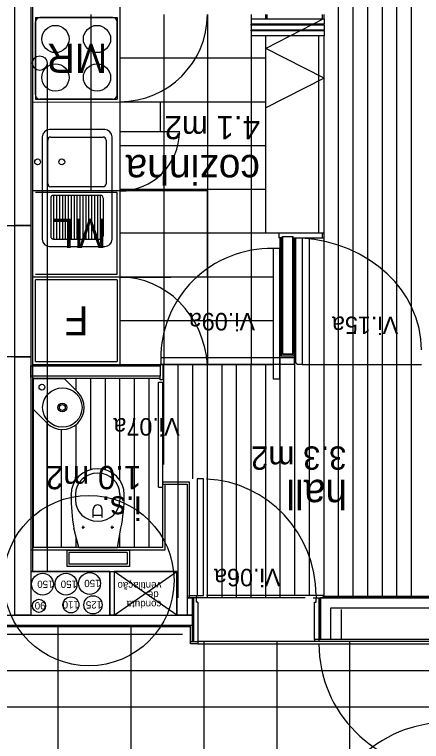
# Model space of a CAD drawing. Extents: x 1248 to 1356, y -443 to -224.
# Drawn here: x 1334.72 to 1337.511, y -239.409 to -234.424 of the extents above; entities that cross this region are included whole.
import ezdxf

# ---------------------------------------------------------------- set-up
doc = ezdxf.new("R2010")
doc.units = 0
for name, color, linetype in [('corte', 7, 'Continuous'), ('estereoctomias', 7, 'Continuous'), ('ind-pormenores', 7, 'Continuous'), ('Level 1', 7, 'Continuous'), ('Level 10', 7, 'Continuous'), ('Level 11', 7, 'Continuous'), ('Level 13', 7, 'Continuous'), ('Level 2', 7, 'Continuous'), ('Level 3', 7, 'Continuous'), ('Level 31', 7, 'Continuous'), ('Level 4', 7, 'Continuous'), ('Level 40', 7, 'Continuous'), ('Level 41', 7, 'Continuous'), ('Level 60', 7, 'Continuous'), ('mob-fixo', 7, 'Continuous'), ('revestimentos', 7, 'Continuous'), ('vista', 7, 'Continuous')]:
    doc.layers.add(name, color=color, linetype=linetype)

msp = doc.modelspace()

# ---------------------------------------------------------------- linework, layer by layer
at = {"layer": 'corte'}
for p, q in [((1334.7233, -238.544), (1334.7233, -232.0639)), ((1335.7533, -238.094), (1335.7533, -237.644)), ((1334.8333, -238.094), (1335.7533, -238.094)), ((1335.3733, -238.244), (1335.3733, -238.544)), ((1335.4033, -238.244), (1335.4033, -238.544)), ((1335.8333, -238.244), (1335.8333, -238.544)), ((1340.0033, -238.424), (1336.8183, -238.424)), ((1332.3825, -238.544), (1335.8333, -238.544)), ((1335.9033, -238.544), (1335.9383, -238.544)), ((1335.9383, -238.614), (1332.3125, -238.614))]:
    msp.add_line(p, q, dxfattribs=at)
msp.add_lwpolyline([(1334.6025, -235.8713), (1334.8325, -235.8713), (1334.8325, -236.7713), (1334.6025, -236.7713)], close=True, dxfattribs=at)
at = {"layer": 'estereoctomias'}
for p, q in [((1335.9033, -237.644), (1335.9033, -238.424)), ((1335.9033, -238.424), (1335.9458, -238.424)), ((1336.7783, -238.724), (1335.9783, -238.724))]:
    msp.add_line(p, q, dxfattribs=at)
for points in [[(1334.8333, -235.8713), (1334.7233, -235.8713), (1334.7233, -232.264), (1334.8333, -232.264), (1334.8325, -235.8713)], [(1336.6283, -236.754), (1336.5583, -236.754), (1336.5583, -235.946), (1336.6283, -235.946), (1336.6283, -236.754)], [(1335.9033, -237.644), (1335.9033, -238.424), (1335.9383, -238.424), (1335.9383, -238.544), (1335.9033, -238.544), (1335.8333, -238.544), (1335.8333, -238.244), (1335.4033, -238.244), (1335.4033, -238.544), (1335.3733, -238.544), (1335.3733, -238.244), (1334.8333, -238.244), (1334.8333, -238.544), (1334.7233, -238.544), (1334.7233, -236.7713), (1334.8333, -236.7713), (1334.8333, -238.094), (1335.7533, -238.094), (1335.7533, -237.644)], [(1340.0733, -236.7713), (1340.0733, -238.4784), (1340.0733, -238.494), (1336.8883, -238.494), (1336.8883, -238.709), (1336.8183, -238.709), (1336.8183, -238.424), (1340.0033, -238.424), (1340.0033, -236.7713)], [(1335.7183, -236.834), (1335.7183, -236.904), (1334.8333, -236.904), (1334.8333, -236.914), (1334.8333, -236.834)], [(1335.9383, -238.544), (1335.9383, -238.614), (1332.3125, -238.614), (1332.3125, -238.494), (1332.3825, -238.494), (1332.3825, -238.544), (1335.9383, -238.544)]]:
    msp.add_lwpolyline(points, close=True, dxfattribs=at)
at = {"layer": 'ind-pormenores'}
msp.add_circle((1335.2301, -238.3059), 0.5842, dxfattribs=at)
at = {"layer": 'Level 1'}
for p, q in [((1334.8333, -232.264), (1334.8333, -238.544)), ((1336.4433, -234.456), (1336.4433, -234.424)), ((1336.4533, -234.456), (1336.4533, -234.424)), ((1336.8333, -234.456), (1336.8333, -234.424)), ((1336.8433, -234.456), (1336.8433, -234.424)), ((1336.8433, -234.456), (1336.4433, -234.456)), ((1336.8433, -235.924), (1336.5333, -235.924)), ((1336.5333, -235.924), (1336.5333, -235.956)), ((1336.6433, -235.924), (1336.5433, -235.924)), ((1336.8333, -235.956), (1336.8333, -235.924)), ((1336.8433, -235.956), (1336.8433, -235.924)), ((1336.5583, -235.956), (1336.5333, -235.956)), ((1336.5583, -235.946), (1336.5583, -236.754)), ((1336.5583, -235.946), (1336.6283, -235.946)), ((1336.6283, -236.754), (1336.6283, -235.946)), ((1336.6283, -235.956), (1336.8433, -235.956)), ((1336.5583, -236.754), (1336.6283, -236.754)), ((1334.8333, -236.834), (1335.7183, -236.834)), ((1335.7183, -236.824), (1335.7183, -236.904)), ((1335.7183, -236.904), (1334.8333, -236.904)), ((1335.7383, -237.644), (1335.9033, -237.644)), ((1335.9033, -237.644), (1335.9033, -238.544)), ((1334.8333, -238.244), (1335.8333, -238.244)), ((1335.9383, -238.424), (1335.9033, -238.424)), ((1335.9383, -238.424), (1335.9383, -238.614)), ((1336.8183, -238.424), (1336.8183, -238.709)), ((1336.8883, -238.494), (1336.8883, -238.709)), ((1337.7283, -238.494), (1336.8883, -238.494)), ((1336.8883, -238.709), (1336.8183, -238.709))]:
    msp.add_line(p, q, dxfattribs=at)
at = {"layer": 'Level 10'}
for p, q in [((1336.9433, -238.409), (1336.9433, -232.274)), ((1337.0433, -238.409), (1337.0433, -232.274)), ((1337.1433, -238.409), (1337.1433, -232.274)), ((1337.2433, -238.409), (1337.2433, -232.274)), ((1337.3433, -238.409), (1337.3433, -232.274)), ((1337.4433, -238.409), (1337.4433, -232.274)), ((1335.7433, -234.424), (1335.7433, -236.824)), ((1336.0433, -234.424), (1336.0433, -236.824)), ((1336.3433, -234.424), (1336.3433, -236.824)), ((1336.4433, -234.724), (1335.4433, -234.724)), ((1336.4433, -235.024), (1335.4433, -235.024)), ((1336.4433, -235.324), (1335.4433, -235.324)), ((1336.4433, -235.624), (1335.4433, -235.624)), ((1336.0433, -236.224), (1336.0433, -235.634)), ((1336.4933, -235.924), (1335.4433, -235.924)), ((1336.5433, -238.424), (1336.5433, -235.956)), ((1336.6433, -238.409), (1336.6433, -235.956)), ((1336.7433, -238.409), (1336.7433, -235.956)), ((1336.8433, -238.409), (1336.8433, -235.956)), ((1336.4933, -236.224), (1335.4433, -236.224)), ((1336.4933, -236.524), (1335.4433, -236.524)), ((1335.7233, -236.824), (1336.4933, -236.824)), ((1335.7433, -237.509), (1335.7433, -236.824)), ((1335.8433, -238.424), (1335.8433, -236.824)), ((1335.9433, -237.609), (1335.9433, -236.824)), ((1336.0433, -238.424), (1336.0433, -236.824)), ((1336.1433, -238.424), (1336.1433, -236.824)), ((1336.2433, -238.424), (1336.2433, -236.824)), ((1336.3433, -238.424), (1336.3433, -236.824)), ((1336.4433, -238.424), (1336.4433, -236.824)), ((1335.1433, -237.0018), (1335.1433, -236.919)), ((1335.2433, -237.5444), (1335.2433, -236.919)), ((1335.3433, -237.5458), (1335.3433, -236.919)), ((1335.4433, -237.6182), (1335.4433, -236.919)), ((1335.5433, -238.079), (1335.5433, -236.919)), ((1335.6433, -238.079), (1335.6433, -236.919)), ((1334.9433, -238.079), (1334.9433, -237.2261)), ((1335.1433, -237.5231), (1335.1433, -237.2351)), ((1335.0433, -238.079), (1335.0433, -237.2689)), ((1335.4433, -238.079), (1335.4433, -237.9819)), ((1335.1433, -238.079), (1335.1433, -238.0102)), ((1336.7133, -238.424), (1335.9133, -238.424)), ((1335.0183, -238.624), (1335.0183, -240.224)), ((1335.5183, -238.624), (1335.5183, -240.224)), ((1332.2525, -238.674), (1335.8733, -238.674)), ((1336.0183, -238.724), (1336.0183, -240.124)), ((1336.5183, -238.724), (1336.5183, -240.124)), ((1337.0183, -238.724), (1337.0183, -240.124)), ((1348.9433, -238.924), (1315.7644, -238.924)), ((1347.9933, -239.174), (1315.7633, -239.174))]:
    msp.add_line(p, q, dxfattribs=at)
at = {"layer": 'Level 11'}
for p, q in [((1335.3934, -234.444), (1334.8934, -234.444)), ((1334.8634, -234.974), (1334.8634, -234.474)), ((1335.4234, -234.974), (1335.4234, -234.474)), ((1335.3934, -235.004), (1334.8934, -235.004)), ((1334.9484, -235.5844), (1334.9484, -235.2844)), ((1334.9684, -235.2644), (1335.3284, -235.2644)), ((1335.3484, -235.2844), (1335.3484, -235.5844)), ((1335.3284, -235.6044), (1334.9684, -235.6044)), ((1334.9684, -235.6828), (1334.9684, -235.9444)), ((1334.9884, -235.6628), (1335.3084, -235.6628)), ((1334.9884, -235.6628), (1334.9884, -235.9644)), ((1335.0084, -235.6628), (1335.0084, -235.9644)), ((1335.0284, -235.6628), (1335.0284, -235.9644)), ((1335.0484, -235.6628), (1335.0484, -235.9644)), ((1335.0684, -235.6628), (1335.0684, -235.9644)), ((1335.0884, -235.6628), (1335.0884, -235.9644)), ((1335.1084, -235.6628), (1335.1084, -235.9644)), ((1335.1284, -235.6628), (1335.1284, -235.9644)), ((1335.1484, -235.6628), (1335.1484, -235.9644)), ((1335.1684, -235.6628), (1335.1684, -235.9644)), ((1335.1884, -235.6628), (1335.1884, -235.9644)), ((1335.2084, -235.6628), (1335.2084, -235.9644)), ((1335.2284, -235.6628), (1335.2284, -235.9644)), ((1335.2484, -235.6628), (1335.2484, -235.9644)), ((1335.2684, -235.6628), (1335.2684, -235.9644)), ((1335.2884, -235.6628), (1335.2884, -235.9644)), ((1335.3084, -235.6628), (1335.3084, -235.9644)), ((1335.3284, -235.6828), (1335.3284, -235.9444)), ((1334.9884, -235.9644), (1335.3084, -235.9644)), ((1335.4233, -236.244), (1334.8633, -236.244)), ((1334.8633, -236.804), (1334.8633, -236.244)), ((1335.4233, -236.244), (1335.4233, -236.804)), ((1334.8633, -236.804), (1335.4233, -236.804)), ((1334.8483, -236.919), (1335.0604, -236.919)), ((1334.8483, -237.1311), (1334.8483, -236.919)), ((1335.1543, -237.0129), (1335.0604, -236.919)), ((1334.9422, -237.225), (1334.8483, -237.1311)), ((1335.1083, -237.7192), (1335.1083, -237.7155)), ((1335.1383, -237.7158), (1335.1383, -237.7519)), ((1335.4433, -237.7158), (1335.4433, -237.7519)), ((1335.4733, -237.7192), (1335.4733, -237.7155)), ((1335.2608, -237.8738), (1335.2608, -237.8166)), ((1335.3208, -237.8738), (1335.3208, -237.8165)), ((1335.2608, -237.8561), (1335.3208, -237.8561)), ((1335.1908, -237.9501), (1335.1908, -237.9301)), ((1335.3908, -237.9501), (1335.3908, -237.9301)), ((1335.1609, -238.079), (1335.1269, -237.9462)), ((1335.1808, -237.9401), (1335.2008, -237.9401)), ((1335.3808, -237.9401), (1335.4008, -237.9401)), ((1335.4256, -238.079), (1335.4498, -237.9462)), ((1335.1609, -238.079), (1335.4256, -238.079)), ((1335.0783, -238.099), (1335.0783, -238.209)), ((1335.5083, -238.099), (1335.0783, -238.099)), ((1335.4933, -238.114), (1335.0933, -238.114)), ((1335.0933, -238.114), (1335.0933, -238.194)), ((1335.4933, -238.114), (1335.4933, -238.194)), ((1335.5083, -238.099), (1335.5083, -238.209)), ((1335.5083, -238.209), (1335.0783, -238.209)), ((1335.4933, -238.194), (1335.0933, -238.194))]:
    msp.add_line(p, q, dxfattribs=at)
for points in [[(1335.339, -235.2132), (1334.9606, -235.2132)], [(1334.9106, -235.2632), (1334.9106, -235.9646)], [(1335.389, -235.9646), (1335.389, -235.2632)], [(1334.9606, -236.0146), (1335.339, -236.0146)]]:
    msp.add_lwpolyline(points, dxfattribs=at)
for centre, radius in [((1335.0007, -234.5918), 0.0936), ((1335.286, -234.5918), 0.0936), ((1335.0007, -234.8561), 0.0936), ((1335.286, -234.8561), 0.0936), ((1334.8784, -235.4344), 0.0199), ((1335.0444, -235.4344), 0.0199), ((1334.9083, -236.979), 0.02), ((1335.0483, -237.119), 0.135), ((1335.0483, -237.119), 0.03), ((1335.0483, -237.119), 0.02)]:
    msp.add_circle(centre, radius, dxfattribs=at)
for centre, radius, start, end in [((1334.8934, -234.474), 0.03, 90, 179.9998), ((1335.3934, -234.474), 0.03, 360, 89.9999), ((1334.8934, -234.974), 0.03, 179.9998, 270.0001), ((1335.3934, -234.974), 0.03, 269.9999, 359.9999), ((1334.9605, -235.2632), 0.05, 90, 180), ((1335.3389, -235.2632), 0.05, 0, 90), ((1334.9684, -235.2844), 0.02, 90, 180), ((1335.3284, -235.2844), 0.02, 0, 90), ((1334.9684, -235.5844), 0.02, 180, 270), ((1335.3284, -235.5844), 0.02, 270, 0), ((1334.9884, -235.6828), 0.02, 90, 180), ((1335.3084, -235.6828), 0.02, 0, 90), ((1334.9605, -235.9646), 0.05, 180, 270), ((1334.9884, -235.9444), 0.02, 180, 270), ((1335.3084, -235.9444), 0.02, 270, 0), ((1335.3389, -235.9646), 0.05, 270, 0), ((1335.0483, -237.119), 0.15, 225.0002, 45), ((1335.2908, -237.8167), 0.03, 359.9987, 180.0005)]:
    msp.add_arc(centre, radius, start, end, dxfattribs=at)
for centre, major_axis, ratio, start_param, end_param in [((1335.2908, -237.7158), (0.1825, 0), 0.972581, 0.000002, 3.141589), ((1335.2908, -237.7158), (0.1525, 0), 0.967187, 0.000002, 3.141589), ((1336.5079, -237.7192), (0, 1.4), 0.999692, 1.570794, 1.733712), ((1333.695, -237.7192), (1.7783, 0), 0.787256, 6.120268, 6.283186), ((1335.2908, -237.7519), (0.1525, 0), 0.967187, 3.141595, 6.283182)]:
    msp.add_ellipse(centre, major_axis=major_axis, ratio=ratio, start_param=start_param, end_param=end_param, dxfattribs=at)
at = {"layer": 'Level 13'}
for p, q in [((1335.4433, -233.727), (1335.4433, -236.824)), ((1336.3433, -234.456), (1336.3433, -234.491)), ((1336.4433, -234.456), (1336.3433, -234.456)), ((1336.8433, -234.491), (1336.3433, -234.491)), ((1336.8433, -234.456), (1336.8433, -234.491)), ((1336.8433, -234.496), (1336.3433, -234.496)), ((1336.3433, -234.496), (1336.3433, -234.531)), ((1336.8433, -234.531), (1336.3433, -234.531)), ((1336.8433, -234.536), (1336.3433, -234.536)), ((1336.3433, -234.536), (1336.3433, -234.571)), ((1336.8433, -234.496), (1336.8433, -234.531)), ((1336.8433, -234.536), (1336.8433, -234.571)), ((1336.8433, -234.571), (1336.3433, -234.571)), ((1336.6483, -235.9582), (1336.6483, -236.804)), ((1336.6933, -235.9582), (1336.6483, -235.9582)), ((1336.6933, -235.9582), (1336.6933, -236.824)), ((1336.5383, -236.029), (1336.4933, -236.029)), ((1336.4933, -236.029), (1336.4933, -236.924)), ((1336.5383, -236.029), (1336.5383, -236.924)), ((1335.4433, -236.224), (1334.8433, -236.224)), ((1336.6933, -236.824), (1336.6683, -236.824)), ((1336.5383, -236.924), (1336.4933, -236.924)), ((1335.7083, -236.944), (1335.7383, -236.944)), ((1335.7083, -237.664), (1335.7083, -236.944)), ((1335.7183, -236.944), (1335.7383, -236.944)), ((1335.7383, -237.664), (1335.7383, -236.944)), ((1335.7383, -237.629), (1335.9183, -237.629)), ((1335.9183, -237.629), (1335.9183, -238.424)), ((1335.9733, -237.609), (1335.9733, -238.409)), ((1336.0173, -237.609), (1335.9733, -237.609)), ((1336.0173, -238.409), (1336.0173, -237.609)), ((1335.7083, -237.664), (1335.7383, -237.664)), ((1335.9183, -238.409), (1335.9683, -238.409)), ((1335.9183, -238.419), (1335.9183, -238.409)), ((1335.9233, -238.419), (1335.9183, -238.419)), ((1335.9233, -238.424), (1335.9233, -238.419)), ((1335.9683, -238.424), (1335.9233, -238.424)), ((1335.9483, -238.424), (1335.9483, -238.724)), ((1335.9683, -238.409), (1335.9683, -238.424)), ((1335.9683, -238.453), (1335.9683, -238.424)), ((1335.9733, -238.409), (1336.0173, -238.409)), ((1336.7683, -238.424), (1336.7883, -238.424)), ((1336.8383, -238.409), (1336.7883, -238.409)), ((1336.7883, -238.409), (1336.7883, -238.424)), ((1336.7883, -238.424), (1336.8333, -238.424)), ((1336.7883, -238.453), (1336.7883, -238.424)), ((1336.8083, -238.424), (1336.8083, -238.709)), ((1336.8333, -238.424), (1336.8333, -238.419)), ((1336.8333, -238.419), (1336.8383, -238.419)), ((1336.8383, -238.419), (1336.8383, -238.409)), ((1335.9783, -238.453), (1335.9683, -238.453)), ((1335.9783, -238.453), (1335.9783, -238.724)), ((1336.7783, -238.709), (1336.7783, -238.453)), ((1336.7783, -238.453), (1336.7883, -238.453)), ((1336.8183, -238.504), (1336.8083, -238.504)), ((1335.9283, -238.739), (1335.9283, -238.614)), ((1335.9383, -238.614), (1335.9383, -238.724)), ((1335.9283, -238.724), (1335.9783, -238.724)), ((1335.9783, -238.724), (1335.9783, -238.739)), ((1337.6833, -238.709), (1336.7783, -238.709)), ((1336.7783, -238.709), (1336.7783, -238.724)), ((1336.8283, -238.724), (1336.7783, -238.724)), ((1336.8083, -238.709), (1336.8083, -238.724)), ((1337.6833, -238.724), (1336.8183, -238.724)), ((1337.6833, -238.724), (1336.8183, -238.724)), ((1337.6833, -238.724), (1336.8283, -238.724)), ((1335.9783, -238.739), (1335.9283, -238.739))]:
    msp.add_line(p, q, dxfattribs=at)
msp.add_arc((1336.6683, -236.804), 0.02, 180, 270, dxfattribs=at)
at = {"layer": 'Level 2'}
for p, q in [((1336.3433, -234.496), (1336.3433, -234.491)), ((1336.8433, -234.496), (1336.8433, -234.491)), ((1336.3433, -234.536), (1336.3433, -234.531)), ((1336.8433, -234.536), (1336.8433, -234.531)), ((1336.4433, -235.924), (1336.4433, -234.571)), ((1336.8433, -235.924), (1336.8433, -234.5671)), ((1336.5433, -235.924), (1336.4433, -235.924))]:
    msp.add_line(p, q, dxfattribs=at)
at = {"layer": 'Level 3'}
for p, q in [((1335.2433, -234.424), (1335.2433, -235.634)), ((1335.4433, -235.634), (1334.8433, -235.634))]:
    msp.add_line(p, q, dxfattribs=at)
at = {"layer": 'Level 31'}
for p, q in [((1335.7383, -236.824), (1335.7183, -236.824)), ((1335.7383, -236.824), (1335.7383, -236.929)), ((1335.7383, -236.929), (1335.7183, -236.929))]:
    msp.add_line(p, q, dxfattribs=at)
at = {"layer": 'Level 4'}
for p, q in [((1334.8633, -234.444), (1335.4233, -234.444)), ((1334.8633, -234.444), (1334.8633, -235.004)), ((1335.4233, -234.444), (1335.4233, -235.004)), ((1336.8433, -234.4521), (1336.4433, -234.6563)), ((1336.8083, -235.924), (1336.8083, -234.5671)), ((1336.8433, -234.8606), (1336.4433, -234.6563)), ((1336.8433, -234.8606), (1336.4433, -235.0648)), ((1334.8433, -235.024), (1335.4433, -235.0216)), ((1334.8633, -235.004), (1335.4233, -235.004)), ((1335.4433, -235.0216), (1335.7207, -235.0216)), ((1335.7207, -235.226), (1335.7207, -235.0216)), ((1335.4433, -235.226), (1335.8513, -235.226)), ((1336.0433, -235.634), (1335.4433, -235.634)), ((1335.4233, -235.644), (1334.8633, -235.644)), ((1335.4233, -236.204), (1335.4233, -235.644)), ((1334.8633, -236.204), (1335.4233, -236.204)), ((1335.4433, -236.224), (1335.7933, -236.224)), ((1336.6383, -236.779), (1335.7233, -236.779)), ((1336.6383, -236.779), (1336.6383, -236.824)), ((1335.7233, -236.789), (1335.7233, -236.824)), ((1336.6383, -236.824), (1335.7233, -236.824)), ((1336.6933, -236.824), (1337.5113, -236.824)), ((1336.7883, -238.409), (1336.0373, -238.409)), ((1336.9608, -238.504), (1336.9608, -238.709)), ((1335.9783, -238.739), (1337.6833, -238.739))]:
    msp.add_line(p, q, dxfattribs=at)
for centre, radius, start, end in [((1335.4433, -234.4216), 0.6, 270, 359.7775), ((1335.4433, -235.226), 0.408, 270, 0), ((1336.4775, -236.7828), 0.7542, 88.8015, 180.4703), ((1337.6833, -240.124), 0.845, 90, 180)]:
    msp.add_arc(centre, radius, start, end, dxfattribs=at)
for centre, major_axis, ratio, start_param, end_param in [((1336.6279, -236.724), (-0.8834, 0), 0.869285, 3.141609, 4.638298), ((1335.4433, -236.8748), (0, 0.6509), 0.924693, 4.790593, 6.283185), ((1336.0031, -238.409), (0, -0.8), 0.981405, 1.570796, 3.098101), ((1337.6633, -238.739), (-0.8551, 0), 0.999998, 0, 1.570796)]:
    msp.add_ellipse(centre, major_axis=major_axis, ratio=ratio, start_param=start_param, end_param=end_param, dxfattribs=at)
at = {"layer": 'Level 41'}
for p, q in [((1335.8333, -238.544), (1335.4033, -238.244)), ((1335.4033, -238.544), (1335.8333, -238.244))]:
    msp.add_line(p, q, dxfattribs=at)
for centre, radius in [((1334.9126, -238.3309), 0.075), ((1335.0735, -238.3309), 0.075), ((1335.2352, -238.3254), 0.075), ((1335.1069, -238.4723), 0.055), ((1335.2586, -238.4723), 0.0625), ((1334.8881, -238.4785), 0.045)]:
    msp.add_circle(centre, radius, dxfattribs=at)
at = {"layer": 'mob-fixo'}
for p, q in [((1334.8433, -234.7569), (1334.8433, -238.244)), ((1334.9433, -234.7569), (1334.9433, -238.244))]:
    msp.add_line(p, q, dxfattribs=at)
msp.add_circle((1334.8933, -234.7569), 0.05, dxfattribs=at)
at = {"layer": 'revestimentos'}
for p, q in [((1334.8433, -232.274), (1334.8433, -236.824)), ((1336.5483, -235.956), (1336.5483, -236.764)), ((1336.6383, -236.764), (1336.6383, -235.956)), ((1336.5483, -236.764), (1336.6383, -236.764)), ((1334.8433, -236.824), (1335.7183, -236.824)), ((1335.7183, -236.919), (1334.8483, -236.919)), ((1334.8483, -236.919), (1334.8483, -238.079)), ((1335.7383, -238.079), (1335.7383, -237.644)), ((1335.7383, -238.079), (1334.8483, -238.079)), ((1339.9933, -238.414), (1336.8383, -238.414)), ((1335.9283, -238.624), (1332.3125, -238.624))]:
    msp.add_line(p, q, dxfattribs=at)
at = {"layer": 'vista'}
msp.add_line((1335.7183, -236.929), (1335.7183, -236.904), dxfattribs=at)

# ---------------------------------------------------------------- texts
at = {"layer": 'Level 11'}
for s, p in [('MR', (1335.357, -234.624)), ('ML', (1335.351, -235.824)), ('F', (1335.2272, -236.424))]:
    msp.add_text(s, height=0.2, rotation=180, dxfattribs=at).set_placement(p)
at = {"layer": 'Level 40'}
for s, p in [('Vi.09a', (1336.3702, -236.4702)), ('Vi.15a', (1337.3519, -236.4951)), ('Vi.07a', (1335.8533, -237.1915)), ('Vi.06a', (1336.5437, -238.2249))]:
    msp.add_text(s, height=0.12, rotation=180, dxfattribs=at).set_placement(p)
at = {"layer": 'Level 41'}
for s, p in [('150', (1334.9876, -238.3059)), ('150', (1335.1485, -238.3059)), ('150', (1335.3102, -238.3004)), ('ventilação ', (1335.7273, -238.3155)), (' de ', (1335.7273, -238.3799)), ('90', (1334.9331, -238.4535)), ('110', (1335.1619, -238.4473)), ('125', (1335.3211, -238.4473)), ('conduta', (1335.7273, -238.4444))]:
    msp.add_text(s, height=0.05, rotation=180, dxfattribs=at).set_placement(p)
at = {"layer": 'Level 60'}
for s, height, p in [('4.1 m2', 0.16, (1336.4036, -235.1187)), ('cozinha', 0.2, (1336.4036, -235.3865)), ('3.3 m2', 0.16, (1336.9966, -237.3856)), ('1.0 m2', 0.16, (1335.5899, -237.5192)), ('hall', 0.2, (1337.0015, -237.6144)), ('i.s.', 0.16, (1335.5899, -237.7282))]:
    msp.add_text(s, height=height, rotation=180, dxfattribs=at).set_placement(p)

doc.saveas('drawing.dxf')
